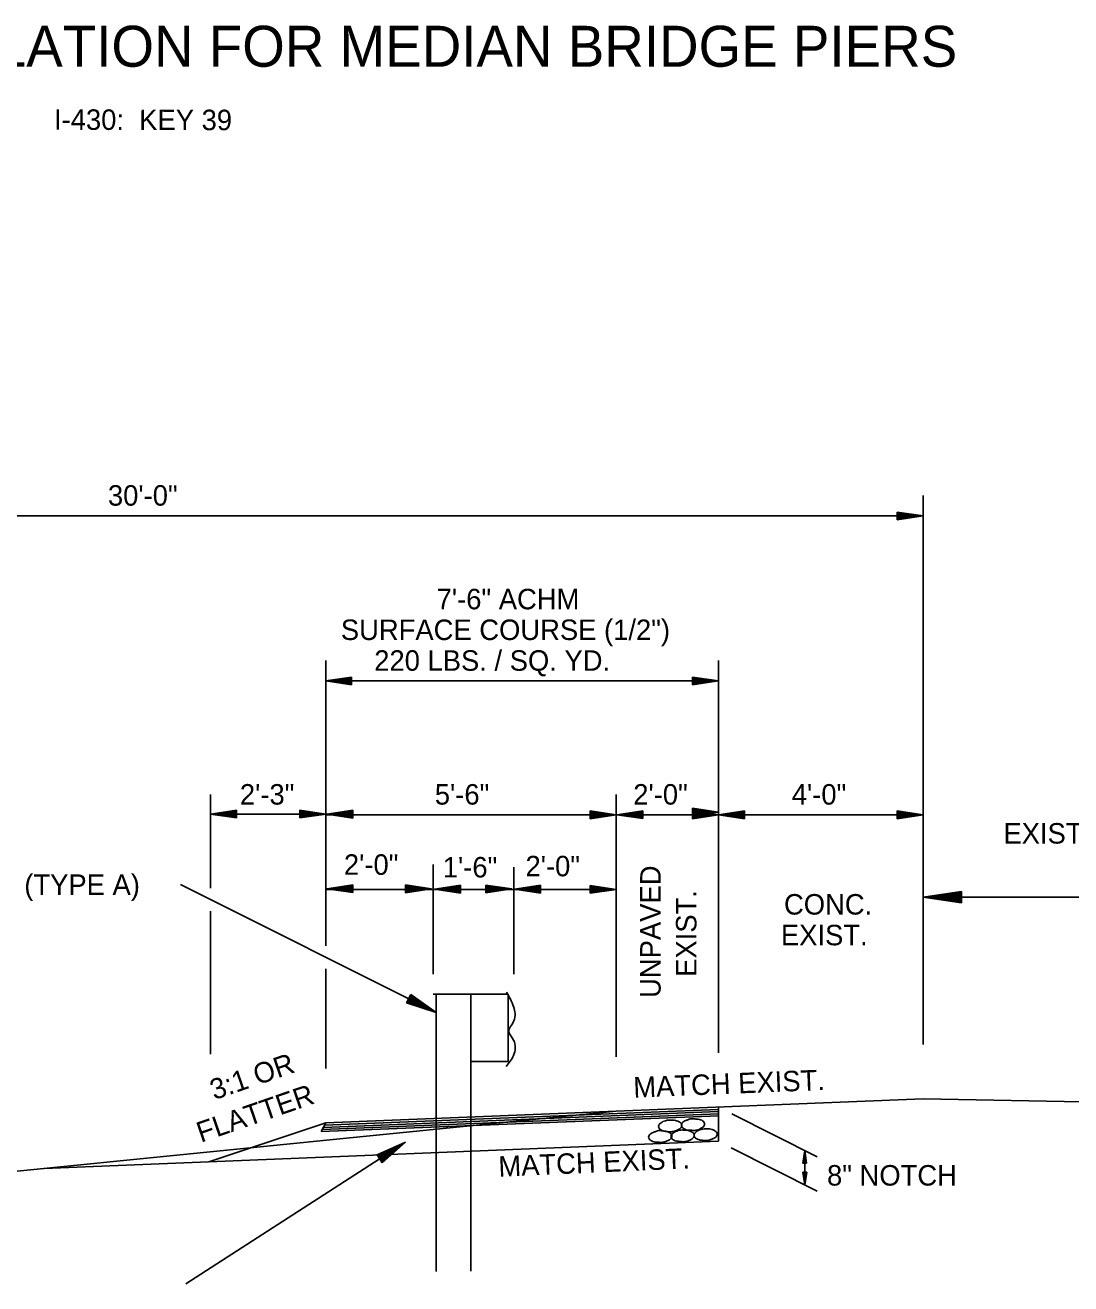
# Model space of a CAD drawing. Extents: x 1373853 to 1374003, y 380191 to 380927.
# Drawn here: x 1373921.8 to 1373952.44, y 380363.25 to 380400.12 of the extents above; entities that cross this region are included whole.
import ezdxf

# ---------------------------------------------------------------- set-up
doc = ezdxf.new("R2010")
doc.units = 0
doc.layers.add('Default', color=7, linetype='Continuous')
doc.layers.add('R_Border Notes', color=7, linetype='Continuous')

msp = doc.modelspace()

# ---------------------------------------------------------------- linework, layer by layer
at = {"layer": 'Default'}
for p, q in [((1373948.117, 380370.258), (1373948.117, 380386.344)), ((1373948.117, 380385.744), (1373903.117, 380385.744)), ((1373947.355, 380385.858), (1373948.117, 380385.744)), ((1373947.355, 380385.628), (1373947.355, 380385.858)), ((1373947.355, 380385.837), (1373947.99, 380385.744)), ((1373947.355, 380385.817), (1373947.858, 380385.744)), ((1373947.355, 380385.799), (1373947.73, 380385.744)), ((1373947.355, 380385.78), (1373947.603, 380385.744)), ((1373947.355, 380385.76), (1373947.474, 380385.744)), ((1373947.355, 380385.628), (1373948.117, 380385.744)), ((1373947.355, 380385.705), (1373947.603, 380385.744)), ((1373947.355, 380385.667), (1373947.858, 380385.744)), ((1373947.355, 380385.648), (1373947.99, 380385.744)), ((1373947.355, 380385.685), (1373947.73, 380385.744)), ((1373947.355, 380385.726), (1373947.474, 380385.744)), ((1373930.608, 380373.153), (1373930.608, 380381.509)), ((1373942.117, 380370.018), (1373942.117, 380381.509)), ((1373931.368, 380381.025), (1373930.608, 380380.909)), ((1373942.117, 380380.909), (1373930.608, 380380.909)), ((1373931.368, 380380.794), (1373930.608, 380380.909)), ((1373931.368, 380381.005), (1373930.735, 380380.909)), ((1373931.368, 380380.815), (1373930.735, 380380.909)), ((1373931.368, 380380.986), (1373930.866, 380380.909)), ((1373931.368, 380380.834), (1373930.866, 380380.909)), ((1373931.368, 380380.966), (1373930.993, 380380.909)), ((1373931.368, 380380.852), (1373930.993, 380380.909)), ((1373931.368, 380380.947), (1373931.121, 380380.909)), ((1373931.368, 380380.873), (1373931.121, 380380.909)), ((1373931.368, 380380.927), (1373931.25, 380380.909)), ((1373931.368, 380380.893), (1373931.25, 380380.909)), ((1373931.368, 380381.025), (1373931.368, 380380.794)), ((1373941.355, 380381.023), (1373942.117, 380380.909)), ((1373941.355, 380380.794), (1373941.355, 380381.023)), ((1373941.355, 380381.002), (1373941.99, 380380.909)), ((1373941.355, 380380.983), (1373941.858, 380380.909)), ((1373941.355, 380380.965), (1373941.73, 380380.909)), ((1373941.355, 380380.945), (1373941.603, 380380.909)), ((1373941.355, 380380.926), (1373941.474, 380380.909)), ((1373941.355, 380380.794), (1373942.117, 380380.909)), ((1373941.355, 380380.87), (1373941.603, 380380.909)), ((1373941.355, 380380.833), (1373941.858, 380380.909)), ((1373941.355, 380380.813), (1373941.99, 380380.909)), ((1373941.355, 380380.851), (1373941.73, 380380.909)), ((1373941.355, 380380.891), (1373941.474, 380380.909)), ((1373927.233, 380374.84), (1373927.233, 380377.589)), ((1373939.117, 380373.101), (1373939.117, 380377.589)), ((1373927.995, 380377.128), (1373927.233, 380377.013)), ((1373930.608, 380377.013), (1373927.233, 380377.013)), ((1373927.995, 380376.899), (1373927.233, 380377.013)), ((1373927.995, 380377.109), (1373927.362, 380377.013)), ((1373927.995, 380376.918), (1373927.362, 380377.013)), ((1373927.995, 380377.089), (1373927.492, 380377.013)), ((1373927.995, 380376.938), (1373927.492, 380377.013)), ((1373927.995, 380377.071), (1373927.62, 380377.013)), ((1373927.995, 380376.956), (1373927.62, 380377.013)), ((1373927.995, 380377.052), (1373927.747, 380377.013)), ((1373927.995, 380376.977), (1373927.747, 380377.013)), ((1373927.995, 380377.031), (1373927.875, 380377.013)), ((1373927.995, 380376.996), (1373927.875, 380377.013)), ((1373927.995, 380377.128), (1373927.995, 380376.899)), ((1373929.846, 380377.127), (1373930.608, 380377.013)), ((1373929.846, 380376.897), (1373929.846, 380377.127)), ((1373929.846, 380377.106), (1373930.48, 380377.013)), ((1373929.846, 380377.086), (1373930.348, 380377.013)), ((1373929.846, 380377.068), (1373930.221, 380377.013)), ((1373929.846, 380377.049), (1373930.093, 380377.013)), ((1373929.846, 380377.029), (1373929.964, 380377.013)), ((1373929.846, 380376.897), (1373930.608, 380377.013)), ((1373929.846, 380376.974), (1373930.093, 380377.013)), ((1373929.846, 380376.936), (1373930.348, 380377.013)), ((1373929.846, 380376.917), (1373930.48, 380377.013)), ((1373929.846, 380376.954), (1373930.221, 380377.013)), ((1373929.846, 380376.995), (1373929.964, 380377.013)), ((1373939.117, 380376.989), (1373930.608, 380376.989)), ((1373931.406, 380377.124), (1373930.645, 380377.008)), ((1373931.406, 380376.893), (1373930.645, 380377.008)), ((1373931.406, 380377.104), (1373930.773, 380377.008)), ((1373931.406, 380376.914), (1373930.773, 380377.008)), ((1373931.406, 380377.085), (1373930.903, 380377.008)), ((1373931.406, 380376.933), (1373930.903, 380377.008)), ((1373931.406, 380377.065), (1373931.031, 380377.008)), ((1373931.406, 380376.951), (1373931.031, 380377.008)), ((1373931.406, 380377.046), (1373931.158, 380377.008)), ((1373931.406, 380376.972), (1373931.158, 380377.008)), ((1373931.406, 380377.026), (1373931.287, 380377.008)), ((1373931.406, 380376.992), (1373931.287, 380377.008)), ((1373931.406, 380377.124), (1373931.406, 380376.893)), ((1373938.355, 380377.103), (1373939.117, 380376.989)), ((1373938.355, 380376.873), (1373938.355, 380377.103)), ((1373938.355, 380377.082), (1373938.99, 380376.989)), ((1373938.355, 380377.062), (1373938.858, 380376.989)), ((1373938.355, 380377.044), (1373938.73, 380376.989)), ((1373938.355, 380377.025), (1373938.603, 380376.989)), ((1373938.355, 380377.005), (1373938.474, 380376.989)), ((1373938.355, 380376.873), (1373939.117, 380376.989)), ((1373938.355, 380376.95), (1373938.603, 380376.989)), ((1373938.355, 380376.912), (1373938.858, 380376.989)), ((1373938.355, 380376.893), (1373938.99, 380376.989)), ((1373938.355, 380376.93), (1373938.73, 380376.989)), ((1373938.355, 380376.971), (1373938.474, 380376.989)), ((1373942.117, 380376.989), (1373939.117, 380376.989)), ((1373939.9, 380377.109), (1373939.138, 380376.993)), ((1373939.9, 380376.879), (1373939.138, 380376.993)), ((1373939.9, 380377.089), (1373939.267, 380376.993)), ((1373939.9, 380376.899), (1373939.267, 380376.993)), ((1373939.9, 380377.07), (1373939.398, 380376.993)), ((1373939.9, 380376.918), (1373939.398, 380376.993)), ((1373939.9, 380377.052), (1373939.525, 380376.993)), ((1373939.9, 380376.936), (1373939.525, 380376.993)), ((1373939.9, 380377.032), (1373939.653, 380376.993)), ((1373939.9, 380376.957), (1373939.653, 380376.993)), ((1373939.9, 380377.011), (1373939.78, 380376.993)), ((1373939.9, 380376.977), (1373939.78, 380376.993)), ((1373939.9, 380377.109), (1373939.9, 380376.879)), ((1373941.355, 380377.181), (1373942.117, 380377.067)), ((1373941.355, 380376.952), (1373941.355, 380377.181)), ((1373941.355, 380377.16), (1373941.99, 380377.067)), ((1373941.355, 380377.141), (1373941.858, 380377.067)), ((1373941.355, 380377.123), (1373941.73, 380377.067)), ((1373941.355, 380377.103), (1373942.117, 380376.989)), ((1373941.355, 380376.873), (1373941.355, 380377.103)), ((1373941.355, 380377.103), (1373941.603, 380377.067)), ((1373941.355, 380377.084), (1373941.474, 380377.067)), ((1373941.355, 380377.083), (1373941.99, 380376.989)), ((1373941.355, 380376.952), (1373942.117, 380377.067)), ((1373941.355, 380377.028), (1373941.603, 380377.067)), ((1373941.355, 380376.991), (1373941.858, 380377.067)), ((1373941.355, 380376.971), (1373941.99, 380377.067)), ((1373941.355, 380377.009), (1373941.73, 380377.067)), ((1373941.355, 380377.049), (1373941.474, 380377.067)), ((1373941.355, 380377.064), (1373941.859, 380376.989)), ((1373941.355, 380377.044), (1373941.732, 380376.989)), ((1373941.355, 380377.025), (1373941.604, 380376.989)), ((1373941.355, 380377.005), (1373941.477, 380376.989)), ((1373941.355, 380376.873), (1373942.117, 380376.989)), ((1373941.355, 380376.95), (1373941.604, 380376.989)), ((1373941.355, 380376.912), (1373941.859, 380376.989)), ((1373941.355, 380376.893), (1373941.99, 380376.989)), ((1373941.355, 380376.932), (1373941.732, 380376.989)), ((1373941.355, 380376.971), (1373941.477, 380376.989)), ((1373942.879, 380377.104), (1373942.117, 380376.989)), ((1373948.117, 380376.989), (1373942.117, 380376.989)), ((1373942.879, 380376.875), (1373942.117, 380376.989)), ((1373942.879, 380377.085), (1373942.246, 380376.989)), ((1373942.879, 380376.894), (1373942.246, 380376.989)), ((1373942.879, 380377.065), (1373942.377, 380376.989)), ((1373942.879, 380376.914), (1373942.377, 380376.989)), ((1373942.879, 380377.047), (1373942.504, 380376.989)), ((1373942.879, 380376.932), (1373942.504, 380376.989)), ((1373942.879, 380377.028), (1373942.632, 380376.989)), ((1373942.879, 380376.953), (1373942.632, 380376.989)), ((1373942.879, 380377.007), (1373942.759, 380376.989)), ((1373942.879, 380376.972), (1373942.759, 380376.989)), ((1373942.879, 380377.104), (1373942.879, 380376.875)), ((1373947.355, 380377.103), (1373948.117, 380376.989)), ((1373947.355, 380376.873), (1373947.355, 380377.103)), ((1373947.355, 380377.083), (1373947.99, 380376.989)), ((1373947.355, 380377.064), (1373947.859, 380376.989)), ((1373947.355, 380377.044), (1373947.732, 380376.989)), ((1373947.355, 380377.025), (1373947.604, 380376.989)), ((1373947.355, 380377.005), (1373947.477, 380376.989)), ((1373947.355, 380376.873), (1373948.117, 380376.989)), ((1373947.355, 380376.95), (1373947.604, 380376.989)), ((1373947.355, 380376.912), (1373947.859, 380376.989)), ((1373947.355, 380376.893), (1373947.99, 380376.989)), ((1373947.355, 380376.932), (1373947.732, 380376.989)), ((1373947.355, 380376.971), (1373947.477, 380376.989)), ((1373939.117, 380369.898), (1373939.117, 380376.203)), ((1373933.756, 380372.325), (1373933.756, 380375.533)), ((1373936.117, 380372.325), (1373936.117, 380375.455)), ((1373926.354, 380374.944), (1373933.843, 380371.2)), ((1373939.117, 380374.807), (1373930.608, 380374.807)), ((1373931.406, 380374.94), (1373930.645, 380374.825)), ((1373931.406, 380374.711), (1373930.645, 380374.825)), ((1373931.406, 380374.921), (1373930.773, 380374.825)), ((1373931.406, 380374.73), (1373930.773, 380374.825)), ((1373931.406, 380374.901), (1373930.903, 380374.825)), ((1373931.406, 380374.75), (1373930.903, 380374.825)), ((1373931.406, 380374.882), (1373931.031, 380374.825)), ((1373931.406, 380374.769), (1373931.031, 380374.825)), ((1373931.406, 380374.862), (1373931.158, 380374.825)), ((1373931.406, 380374.789), (1373931.158, 380374.825)), ((1373931.406, 380374.843), (1373931.287, 380374.825)), ((1373931.406, 380374.808), (1373931.287, 380374.825)), ((1373931.406, 380374.94), (1373931.406, 380374.711)), ((1373932.946, 380374.936), (1373933.708, 380374.822)), ((1373932.946, 380374.706), (1373932.946, 380374.936)), ((1373932.946, 380374.916), (1373933.581, 380374.822)), ((1373932.946, 380374.897), (1373933.449, 380374.822)), ((1373932.946, 380374.877), (1373933.321, 380374.822)), ((1373932.946, 380374.858), (1373933.194, 380374.822)), ((1373932.946, 380374.84), (1373933.066, 380374.822)), ((1373932.946, 380374.706), (1373933.708, 380374.822)), ((1373932.946, 380374.784), (1373933.194, 380374.822)), ((1373932.946, 380374.745), (1373933.449, 380374.822)), ((1373932.946, 380374.726), (1373933.581, 380374.822)), ((1373932.946, 380374.765), (1373933.321, 380374.822)), ((1373932.946, 380374.804), (1373933.066, 380374.822)), ((1373934.559, 380374.928), (1373933.798, 380374.813)), ((1373934.559, 380374.699), (1373933.798, 380374.813)), ((1373934.559, 380374.909), (1373933.926, 380374.813)), ((1373934.559, 380374.718), (1373933.926, 380374.813)), ((1373934.559, 380374.888), (1373934.056, 380374.813)), ((1373934.559, 380374.738), (1373934.056, 380374.813)), ((1373934.559, 380374.871), (1373934.184, 380374.813)), ((1373934.559, 380374.756), (1373934.184, 380374.813)), ((1373934.559, 380374.85), (1373934.311, 380374.813)), ((1373934.559, 380374.775), (1373934.311, 380374.813)), ((1373934.559, 380374.831), (1373934.44, 380374.813)), ((1373934.559, 380374.796), (1373934.44, 380374.813)), ((1373934.559, 380374.928), (1373934.559, 380374.699)), ((1373935.3, 380374.934), (1373936.063, 380374.82)), ((1373935.3, 380374.705), (1373935.3, 380374.934)), ((1373935.3, 380374.915), (1373935.934, 380374.82)), ((1373935.3, 380374.895), (1373935.804, 380374.82)), ((1373935.3, 380374.876), (1373935.676, 380374.82)), ((1373935.3, 380374.856), (1373935.549, 380374.82)), ((1373935.3, 380374.837), (1373935.421, 380374.82)), ((1373935.3, 380374.705), (1373936.063, 380374.82)), ((1373935.3, 380374.781), (1373935.549, 380374.82)), ((1373935.3, 380374.744), (1373935.804, 380374.82)), ((1373935.3, 380374.724), (1373935.934, 380374.82)), ((1373935.3, 380374.763), (1373935.676, 380374.82)), ((1373935.3, 380374.802), (1373935.421, 380374.82)), ((1373936.9, 380374.927), (1373936.138, 380374.811)), ((1373936.9, 380374.697), (1373936.138, 380374.811)), ((1373936.9, 380374.907), (1373936.267, 380374.811)), ((1373936.9, 380374.717), (1373936.267, 380374.811)), ((1373936.9, 380374.888), (1373936.398, 380374.811)), ((1373936.9, 380374.736), (1373936.398, 380374.811)), ((1373936.9, 380374.87), (1373936.525, 380374.811)), ((1373936.9, 380374.754), (1373936.525, 380374.811)), ((1373936.9, 380374.85), (1373936.653, 380374.811)), ((1373936.9, 380374.775), (1373936.653, 380374.811)), ((1373936.9, 380374.829), (1373936.78, 380374.811)), ((1373936.9, 380374.795), (1373936.78, 380374.811)), ((1373936.9, 380374.927), (1373936.9, 380374.697)), ((1373938.355, 380374.921), (1373939.117, 380374.807)), ((1373938.355, 380374.691), (1373938.355, 380374.921)), ((1373938.355, 380374.901), (1373938.99, 380374.807)), ((1373938.355, 380374.882), (1373938.859, 380374.807)), ((1373938.355, 380374.862), (1373938.732, 380374.807)), ((1373938.355, 380374.843), (1373938.604, 380374.807)), ((1373938.355, 380374.823), (1373938.477, 380374.807)), ((1373938.355, 380374.691), (1373939.117, 380374.807)), ((1373938.355, 380374.768), (1373938.604, 380374.807)), ((1373938.355, 380374.73), (1373938.859, 380374.807)), ((1373938.355, 380374.711), (1373938.99, 380374.807)), ((1373938.355, 380374.75), (1373938.732, 380374.807)), ((1373938.355, 380374.789), (1373938.477, 380374.807)), ((1373949.243, 380374.747), (1373948.118, 380374.579)), ((1373949.243, 380374.718), (1373948.306, 380374.579)), ((1373949.243, 380374.69), (1373948.499, 380374.579)), ((1373949.243, 380374.663), (1373948.687, 380374.579)), ((1373949.243, 380374.409), (1373949.243, 380374.747)), ((1373948.117, 380374.578), (1373960.989, 380374.578)), ((1373949.243, 380374.409), (1373948.118, 380374.579)), ((1373949.243, 380374.438), (1373948.306, 380374.579)), ((1373949.243, 380374.466), (1373948.499, 380374.579)), ((1373949.243, 380374.495), (1373948.687, 380374.579)), ((1373949.243, 380374.633), (1373948.877, 380374.579)), ((1373949.243, 380374.523), (1373948.877, 380374.579)), ((1373949.243, 380374.604), (1373949.065, 380374.579)), ((1373949.243, 380374.552), (1373949.065, 380374.579)), ((1373927.233, 380369.976), (1373927.233, 380374.169)), ((1373939.117, 380369.898), (1373939.117, 380373.101)), ((1373930.608, 380369.558), (1373930.608, 380372.482)), ((1373932.978, 380371.482), (1373933.099, 380371.723)), ((1373933.089, 380371.703), (1373933.709, 380371.267)), ((1373933.099, 380371.723), (1373933.843, 380371.2)), ((1373935.958, 380371.736), (1373933.756, 380371.736)), ((1373933.843, 380371.727), (1373933.843, 380363.618)), ((1373934.857, 380371.736), (1373934.857, 380363.626)), ((1373935.958, 380371.736), (1373935.958, 380369.767)), ((1373932.978, 380371.482), (1373933.843, 380371.2)), ((1373932.988, 380371.502), (1373933.709, 380371.267)), ((1373932.998, 380371.523), (1373933.57, 380371.337)), ((1373933.008, 380371.543), (1373933.436, 380371.404)), ((1373933.019, 380371.564), (1373933.3, 380371.472)), ((1373933.029, 380371.584), (1373933.166, 380371.539)), ((1373933.048, 380371.622), (1373933.166, 380371.539)), ((1373933.058, 380371.642), (1373933.3, 380371.472)), ((1373933.068, 380371.663), (1373933.436, 380371.404)), ((1373933.078, 380371.683), (1373933.57, 380371.337)), ((1373935.958, 380369.767), (1373934.857, 380369.767)), ((1373948.117, 380368.673), (1373939.117, 380368.313)), ((1373942.117, 380367.427), (1373942.117, 380368.433)), ((1373948.117, 380368.673), (1373960.989, 380368.415)), ((1373942.117, 380368.177), (1373930.478, 380367.712)), ((1373942.115, 380368.237), (1373930.508, 380367.773)), ((1373942.113, 380368.297), (1373930.539, 380367.834)), ((1373942.11, 380368.357), (1373930.57, 380367.896)), ((1373939.117, 380368.313), (1373930.608, 380367.972)), ((1373942.508, 380368.235), (1373945.006, 380366.976)), ((1373927.182, 380366.829), (1373930.608, 380367.972)), ((1373930.608, 380367.972), (1373930.478, 380367.712)), ((1373942.117, 380367.427), (1373922.354, 380366.636)), ((1373926.508, 380363.253), (1373932.949, 380367.402)), ((1373932.119, 380367.028), (1373932.949, 380367.402)), ((1373932.132, 380367.01), (1373932.823, 380367.321)), ((1373932.253, 380366.82), (1373932.823, 380367.321)), ((1373932.266, 380366.801), (1373932.949, 380367.402)), ((1373932.266, 380366.801), (1373932.119, 380367.028)), ((1373932.144, 380366.99), (1373932.693, 380367.237)), ((1373932.156, 380366.971), (1373932.567, 380367.156)), ((1373932.169, 380366.952), (1373932.438, 380367.073)), ((1373932.181, 380366.933), (1373932.312, 380366.992)), ((1373932.204, 380366.897), (1373932.312, 380366.992)), ((1373932.216, 380366.878), (1373932.438, 380367.073)), ((1373932.229, 380366.859), (1373932.567, 380367.156)), ((1373932.241, 380366.84), (1373932.693, 380367.237)), ((1373942.492, 380367.238), (1373945.008, 380365.968)), ((1373944.586, 380366.783), (1373944.644, 380367.158)), ((1373944.595, 380366.783), (1373944.644, 380367.095)), ((1373944.605, 380366.783), (1373944.643, 380367.031)), ((1373944.614, 380366.783), (1373944.643, 380366.968)), ((1373944.624, 380366.783), (1373944.643, 380366.905)), ((1373944.679, 380366.783), (1373944.643, 380367.031)), ((1373944.67, 380366.783), (1373944.643, 380366.968)), ((1373944.66, 380366.783), (1373944.643, 380366.905)), ((1373944.644, 380366.152), (1373944.644, 380367.158)), ((1373944.698, 380366.783), (1373944.644, 380367.158)), ((1373944.689, 380366.783), (1373944.644, 380367.095)), ((1373944.698, 380366.783), (1373944.586, 380366.783)), ((1373944.59, 380366.528), (1373944.644, 380366.152)), ((1373944.59, 380366.528), (1373944.703, 380366.527)), ((1373944.6, 380366.527), (1373944.645, 380366.215)), ((1373944.609, 380366.527), (1373944.645, 380366.279)), ((1373944.619, 380366.527), (1373944.645, 380366.342)), ((1373944.628, 380366.527), (1373944.646, 380366.405)), ((1373944.633, 380366.783), (1373944.642, 380366.842)), ((1373944.638, 380366.527), (1373944.646, 380366.468)), ((1373944.651, 380366.783), (1373944.642, 380366.842)), ((1373944.703, 380366.527), (1373944.644, 380366.152)), ((1373944.684, 380366.527), (1373944.645, 380366.279)), ((1373944.693, 380366.527), (1373944.645, 380366.215)), ((1373944.674, 380366.527), (1373944.645, 380366.342)), ((1373944.665, 380366.527), (1373944.646, 380366.405)), ((1373944.655, 380366.527), (1373944.646, 380366.468))]:
    msp.add_line(p, q, dxfattribs=at)
for points in [[(1373935.906, 380371.799), (1373936.113, 380371.372), (1373936.123, 380370.956), (1373935.975, 380370.634), (1373936.113, 380370.391), (1373936.113, 380369.942), (1373935.894, 380369.618)], [(1373940.696, 380368.047), (1373940.816, 380368.045), (1373940.963, 380368), (1373941.036, 380367.932), (1373941.048, 380367.892), (1373941.009, 380367.815), (1373940.97, 380367.782), (1373940.89, 380367.744), (1373940.774, 380367.713), (1373940.712, 380367.705), (1373940.624, 380367.711), (1373940.526, 380367.727), (1373940.449, 380367.755), (1373940.375, 380367.813), (1373940.363, 380367.86), (1373940.384, 380367.926), (1373940.438, 380367.97), (1373940.489, 380368.004), (1373940.568, 380368.031), (1373940.619, 380368.042), (1373940.696, 380368.047)], [(1373941.357, 380368.088), (1373941.484, 380368.076), (1373941.627, 380368.042), (1373941.701, 380367.973), (1373941.713, 380367.934), (1373941.677, 380367.856), (1373941.634, 380367.823), (1373941.555, 380367.778), (1373941.439, 380367.747), (1373941.38, 380367.746), (1373941.289, 380367.752), (1373941.187, 380367.758), (1373941.11, 380367.793), (1373941.043, 380367.854), (1373941.032, 380367.901), (1373941.052, 380367.967), (1373941.106, 380368.012), (1373941.157, 380368.034), (1373941.237, 380368.068), (1373941.284, 380368.084), (1373941.357, 380368.088)], [(1373940.404, 380367.74), (1373940.524, 380367.727), (1373940.671, 380367.689), (1373940.745, 380367.624), (1373940.756, 380367.581), (1373940.717, 380367.507), (1373940.678, 380367.474), (1373940.598, 380367.429), (1373940.486, 380367.398), (1373940.424, 380367.397), (1373940.333, 380367.403), (1373940.234, 380367.409), (1373940.157, 380367.44), (1373940.083, 380367.505), (1373940.072, 380367.548), (1373940.092, 380367.614), (1373940.146, 380367.659), (1373940.201, 380367.685), (1373940.28, 380367.716), (1373940.327, 380367.735), (1373940.404, 380367.74)], [(1373941.059, 380367.759), (1373941.18, 380367.75), (1373941.326, 380367.709), (1373941.396, 380367.644), (1373941.408, 380367.601), (1373941.373, 380367.527), (1373941.337, 380367.494), (1373941.253, 380367.456), (1373941.141, 380367.418), (1373941.079, 380367.417), (1373940.988, 380367.423), (1373940.886, 380367.436), (1373940.812, 380367.46), (1373940.738, 380367.525), (1373940.727, 380367.568), (1373940.748, 380367.634), (1373940.802, 380367.679), (1373940.856, 380367.712), (1373940.932, 380367.743), (1373940.983, 380367.755), (1373941.059, 380367.759)], [(1373941.733, 380367.791), (1373941.853, 380367.789), (1373942, 380367.741), (1373942.07, 380367.676), (1373942.082, 380367.632), (1373942.047, 380367.559), (1373942.003, 380367.525), (1373941.927, 380367.488), (1373941.808, 380367.453), (1373941.749, 380367.449), (1373941.658, 380367.455), (1373941.559, 380367.471), (1373941.482, 380367.499), (1373941.412, 380367.556), (1373941.401, 380367.6), (1373941.422, 380367.666), (1373941.476, 380367.711), (1373941.526, 380367.748), (1373941.606, 380367.775), (1373941.657, 380367.786), (1373941.733, 380367.791)]]:
    msp.add_spline(points, degree=3, dxfattribs=at)
at = {"layer": 'R_Border Notes'}
msp.add_line((1373939.117, 380368.313), (1373903.117, 380364.713), dxfattribs=at)

# ---------------------------------------------------------------- texts
at = {"layer": 'Default'}
for s, height, rotation, p in [('PARALLEL GUARDRAIL INSTALLATION FOR MEDIAN BRIDGE PIERS', 1.2, 359.9999, (1373896.95, 380398.899)), ('I-430:  KEY 39', 0.6, 359.8564, (1373922.645, 380397.053)), ('UNPAVED', 0.6, 90, (1373940.423, 380371.627)), ('EXIST.', 0.6, 90, (1373941.473, 380372.244)), ('3:1 OR', 0.6, 19.0365, (1373927.344, 380368.631)), ('MATCH EXIST.', 0.6, 2.3106, (1373939.634, 380368.705)), ('FLATTER', 0.6, 19.0365, (1373926.95, 380367.384)), ('MATCH EXIST.', 0.6, 2.5087, (1373935.681, 380366.388))]:
    msp.add_text(s, height=height, rotation=rotation, dxfattribs=at).set_placement(p)
for s, p in [('30\'-0"', (1373924.226, 380386.044)), ('7\'-6" ACHM', (1373933.859, 380383.009)), ('SURFACE COURSE (1/2")', (1373931.052, 380382.109)), ('220 LBS. / SQ. YD.', (1373932.03, 380381.209)), ('2\'-3"', (1373928.093, 380377.289)), ('5\'-6"', (1373933.805, 380377.289)), ('2\'-0"', (1373939.621, 380377.289)), ('4\'-0"', (1373944.266, 380377.289)), ('EXISTING PAVEMENT', (1373950.469, 380376.147)), ('2\'-0"', (1373931.141, 380375.233)), ('1\'-6"', (1373934.039, 380375.155)), ('2\'-0"', (1373936.463, 380375.188)), ('GUARDRAIL (TYPE A)', (1373916.871, 380374.644)), ('CONC.', (1373944.038, 380374.068)), ('EXIST.', (1373943.948, 380373.168)), ('8" NOTCH', (1373945.299, 380366.131))]:
    msp.add_text(s, height=0.6, dxfattribs=at).set_placement(p)

doc.saveas('drawing.dxf')
